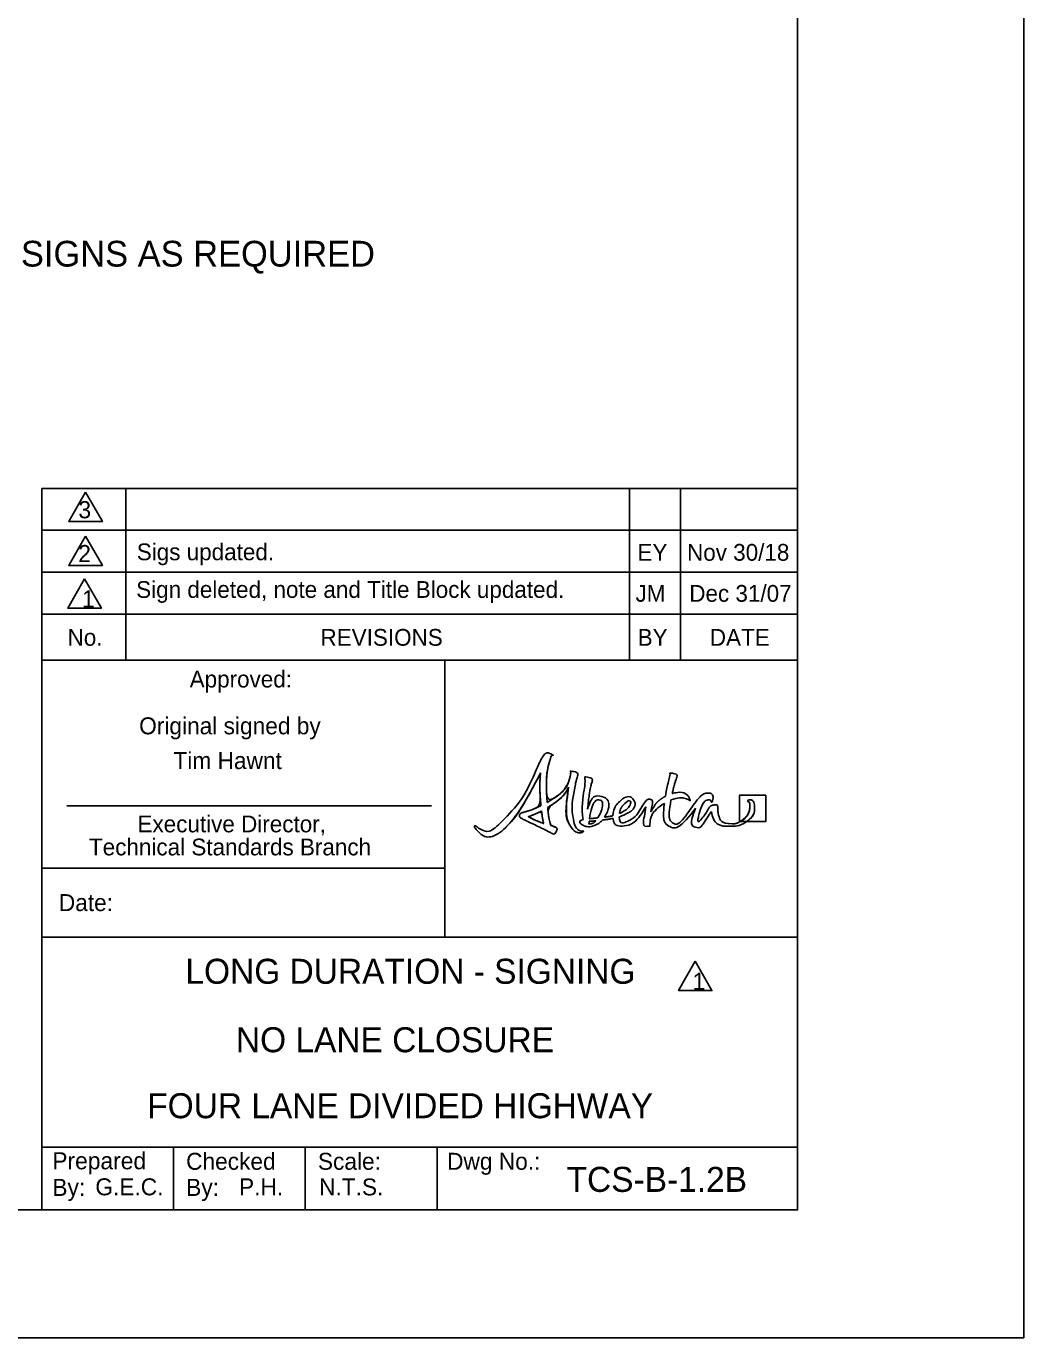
# Model space of a CAD drawing. Extents: x 1381 to 1597, y 125 to 404.
# Drawn here: x 1512.9 to 1597.2, y 124.9 to 235.9 of the extents above; entities that cross this region are included whole.
import ezdxf

# ---------------------------------------------------------------- set-up
doc = ezdxf.new("R2010")
doc.units = 0
for name, color, linetype in [('Level 10', 7, 'Continuous'), ('Level 22', 7, 'Continuous'), ('Level 44', 7, 'Continuous'), ('Level 53', 7, 'Continuous'), ('Level 60', 7, 'Continuous'), ('Level 7', 7, 'Continuous')]:
    doc.layers.add(name, color=color, linetype=linetype)

# ---------------------------------------------------------------- blocks, each defined once
blk = doc.blocks.new('Alberta Signature')
at = {"layer": 'Level 53'}
blk.add_line((-5.9, -14.5), (-13.3, -14.5), dxfattribs=at)
blk.add_lwpolyline([(-5.9, -14.5), (15.6, -14.5), (15.6, 15.2), (-14.1, 15.2), (-14.1, -14.5), (-13.3, -14.5)], dxfattribs=at)
for points, degree in [([(-192.4, -25.3), (-195.6, -24.8), (-199.8, -20.5), (-201, -13.3), (-203.3, -0.4), (-202, 12.3), (-198.2, 31.2), (-197.5, 34.8), (-195, 41), (-202.8, 42.2), (-205.3, 42.6), (-204, 41.4), (-204.7, 38.1), (-207.7, 24), (-219.2, 13.8), (-230.8, 7), (-232, 23.2), (-231.5, 41.1), (-228.5, 52.1), (-225.9, 61.4), (-222.9, 59.7), (-226.7, 61.7), (-230.6, 63.7), (-234.9, 61), (-238.4, 54.1), (-241.8, 47.2), (-257.8, 9.6), (-283.3, -15.7), (-296.3, -28.7), (-308.1, -22), (-310.5, -20), (-312.4, -18.4), (-313.1, -20.9), (-310.7, -23.5), (-300.2, -34.8), (-284.8, -28.3), (-279.2, -22.7), (-263.7, -7.2), (-245.6, 26.2), (-238.3, 40.3), (-239, 32.3), (-239.2, 19), (-237.8, 3.3), (-245.7, -0.5), (-252.7, -2.8), (-256.1, -3.7), (-259.7, -4.6), (-261.9, -6.1), (-262, -7.8), (-262.1, -9.6), (-259.6, -11.2), (-256.1, -12.8), (-249.9, -15.8), (-231.6, -24.4), (-227.1, -27), (-223.2, -29.3), (-221.3, -27.5), (-220.2, -25.1), (-218.7, -22), (-222.8, -20.2), (-226.8, -19), (-228.3, -13.7), (-229.5, -6.5), (-230.3, 1.3), (-221, 7.1), (-211.9, 14.7), (-206.6, 24.2), (-207.9, 16.3), (-211.3, -10.8), (-202.8, -22.3), (-200.9, -24.8), (-196.7, -27.5), (-192.7, -27.1), (-190.8, -26.9), (-189.8, -25.7), (-190, -25.3), (-190.2, -24.9), (-191.3, -25.5), (-192.4, -25.3)], 3), ([(-230.8, 7), (-232, 23.2), (-231.5, 41.1), (-228.5, 52.1), (-225.9, 61.4), (-222.9, 59.7), (-226.7, 61.7), (-230.6, 63.7), (-234.9, 61), (-238.4, 54.1), (-241.8, 47.2), (-257.8, 9.6), (-283.3, -15.7), (-296.3, -28.7), (-308.1, -22), (-310.5, -20), (-312.4, -18.4), (-313.1, -20.9), (-310.7, -23.5), (-300.2, -34.8), (-284.8, -28.3), (-279.2, -22.7), (-263.7, -7.2), (-245.6, 26.2), (-238.3, 40.3)], 3), ([(-238.3, 40.3), (-239, 32.3), (-239.2, 19), (-237.8, 3.3)], 2), ([(-192.4, -25.3), (-195.6, -24.8), (-199.8, -20.5), (-201, -13.3), (-203.3, -0.4), (-202, 12.3), (-198.2, 31.2), (-197.5, 34.8), (-195, 41), (-202.8, 42.2), (-205.3, 42.6), (-204, 41.4), (-204.7, 38.1), (-207.7, 24), (-219.2, 13.8), (-230.8, 7)], 3), ([(-185.2, -0.7), (-184.6, 6.9), (-183.4, 16.1), (-181.7, 24.7), (-181, 28.2), (-178.5, 34.4), (-186.3, 35.6), (-188.8, 36), (-188.4, 34.9), (-188.2, 31.5), (-187.9, 27), (-192.9, -0.2), (-190.3, -12.1)], 3), ([(-89.8, 17.1), (-89, 21.1), (-88, 25.1), (-86.9, 29.1), (-85.9, 32.6), (-82.9, 38.9), (-90.6, 40), (-93.1, 40.4), (-92, 39.2), (-92.8, 35.9), (-94.3, 29.8), (-96.2, 21.9), (-97.5, 14)], 3), ([(-230.3, 1.3), (-221, 7.1), (-211.9, 14.7), (-206.6, 24.2)], 2), ([(-206.6, 24.2), (-207.9, 16.3), (-211.3, -10.8), (-202.8, -22.3), (-200.9, -24.8), (-196.7, -27.5), (-192.7, -27.1), (-190.8, -26.9), (-189.8, -25.7), (-190, -25.3), (-190.2, -24.9), (-191.3, -25.5), (-192.4, -25.3)], 3), ([(-166.1, -9.6), (-160.5, -0.6), (-161, 11.5), (-169.1, 13.6), (-178.5, 16), (-183.2, 6.8), (-185.2, -0.7)], 3), ([(-22.5, -17.1), (-34.7, -17.1), (-37.8, -7.7), (-38.4, -3), (-38.8, 0.2), (-38.1, 4.7), (-43.5, 4.1), (-47.3, 3.7), (-50.7, -3.7), (-55.5, -9.9), (-59.6, -15.2), (-61.4, -14.7), (-60.5, -10.1), (-59.3, -4.4), (-54.5, 9), (-49.1, 10), (-46.5, 10.4), (-45.6, 6), (-44.5, 8.8), (-43.3, 11.5), (-44.4, 17.5), (-50, 17.5), (-54, 17.5), (-58.7, 13.3), (-62.6, 8.6), (-66, 4.4), (-83.1, -20.8), (-90.3, -15.4), (-93.7, -12.8), (-93.4, -2.5), (-91.3, 9.8)], 3), ([(-91.3, 9.8), (-82.8, 13), (-75.7, 12), (-71.7, 10), (-69.7, 9.1), (-69.4, 9.2), (-70.3, 11.4), (-71.5, 14.6), (-78.4, 19.6), (-89.1, 17.3), (-89.3, 17.3), (-89.6, 17.2), (-89.8, 17.1)], 3), ([(-14.1, 15.2), (-14.1, 15.2), (-14.1, -14.5), (-14.1, -14.5), (-14.1, -14.5), (-13.3, -14.5), (-13.3, -14.5), (-6.8, -10.6), (-2.5, -3.2), (-2.5, 2.8), (-2.5, 8.1), (-5.3, 7.8), (-4.9, 8.6), (-4, 10.7), (2.5, 9.5), (2.9, 2), (3.2, -4.2), (-0.1, -10.3), (-5.9, -14.5), (-5.9, -14.5), (15.6, -14.5), (15.6, -14.5), (15.6, -14.5), (15.6, 15.2), (15.6, 15.2), (15.6, 15.2), (-14.1, 15.2), (-14.1, 15.2)], 3), ([(-237.8, 3.3), (-245.7, -0.5), (-252.7, -2.8), (-256.1, -3.7), (-259.7, -4.6), (-261.9, -6.1), (-262, -7.8), (-262.1, -9.6), (-259.6, -11.2), (-256.1, -12.8), (-249.9, -15.8), (-231.6, -24.4), (-227.1, -27), (-223.2, -29.3), (-221.3, -27.5), (-220.2, -25.1), (-218.7, -22), (-222.8, -20.2), (-226.8, -19)], 3), ([(-226.8, -19), (-228.3, -13.7), (-229.5, -6.5), (-230.3, 1.3)], 2), ([(-183.2, -11.3), (-182, -1.7), (-177, 11.5), (-170.8, 9.4), (-167.3, 8.2), (-169.1, -3), (-173.7, -10.4)], 3), ([(-149.7, -9.2), (-148.4, -8.9), (-147.3, -8.5), (-146.3, -8), (-134.5, -2.8), (-130.5, 5.1), (-133.5, 9.9), (-136.3, 14.4), (-144.5, 13), (-150.9, 6.3), (-154, 2.9), (-156.5, -2.8), (-156.7, -8)], 3), ([(-156.6, -10.9), (-156, -16.2), (-152.6, -20.2), (-144.6, -19.4), (-133.4, -18.4), (-123.3, -4.5), (-119.6, 2.2)], 3), ([(-114.1, -3.7), (-113.3, 0), (-112.2, 4), (-112.1, 6.8), (-112, 9.7), (-114, 10.3), (-114.8, 10.6), (-116.4, 11), (-118.5, 10.2), (-120.5, 7.4), (-125.2, 0.7), (-131.2, -9.8), (-140.2, -14.2), (-146.7, -17.3), (-149.6, -14.1), (-149.7, -9.2)], 3), ([(-143.4, 5.7), (-139.5, 9.3), (-137.5, 9.1), (-137, 8.1), (-135.9, 6), (-140.5, -1.5), (-149.4, -5.6)], 3), ([(-149.4, -5.6), (-148.7, -1.6), (-146.5, 2.8), (-143.4, 5.7)], 2), ([(-119.6, 2.2), (-120.2, -5), (-124.9, -20.6), (-117, -19.8), (-113.8, -19.5), (-115.2, -19), (-115, -16.3), (-114.3, -6.9), (-106.5, 1.1), (-98.7, 6)], 3), ([(-97.5, 14), (-103.9, 10.4), (-109.7, 4.3), (-114.1, -3.7)], 2), ([(-98.7, 6), (-100.1, -5.6), (-99.6, -15.9), (-94.4, -19.1), (-84.7, -25.2), (-71.1, -9.3), (-63.6, 0.4)], 3), ([(-63.6, 0.4), (-67.4, -8.2), (-69.6, -19.3), (-63.8, -20.9), (-57.1, -22.9), (-51.8, -11.7), (-45.6, -3.2)], 3), ([(-13.3, -14.5), (-6.8, -10.6), (-2.5, -3.2), (-2.5, 2.8), (-2.5, 8.1), (-5.3, 7.8), (-4.9, 8.6), (-4, 10.7), (2.5, 9.5), (2.9, 2), (3.2, -4.2), (-0.1, -10.3), (-5.9, -14.5)], 3), ([(-252, -9.1), (-247.9, -7.6), (-242.7, -5.4), (-237.1, -2.5)], 2), ([(-252, -9.1), (-247.9, -7.6), (-242.7, -5.4), (-237.1, -2.5), (-236.4, -8.8), (-235.6, -13.4), (-234.7, -16.8), (-238.7, -15.3), (-244.5, -13), (-252, -9.1)], 3), ([(-234.7, -16.8), (-238.7, -15.3), (-244.5, -13), (-252, -9.1)], 2), ([(-237.1, -2.5), (-236.4, -8.8), (-235.6, -13.4), (-234.7, -16.8)], 2), ([(-190.3, -12.1), (-193.6, -13.2), (-195, -15.7), (-190.7, -18.4), (-187.7, -20.2), (-181.2, -20.8), (-174.6, -17.5), (-172.2, -16.4), (-170.2, -14.7), (-168.5, -12.8)], 3), ([(-184.2, -17), (-183.8, -16.7), (-183.5, -16.1), (-183.5, -15.5), (-183.5, -15.1), (-183.5, -14.7), (-183.5, -14.2)], 3), ([(-183.5, -14.2), (-181.8, -14.2), (-179.2, -14), (-176.1, -13.7)], 2), ([(-173.7, -10.4), (-176.7, -10.7), (-179.9, -11), (-183.2, -11.3)], 2), ([(-176.1, -13.7), (-177.7, -15.5), (-179.6, -16.7), (-181.5, -17)], 2), ([(-168.5, -12.8), (-164.5, -12.3), (-160.4, -11.7), (-156.6, -10.9)], 2), ([(-156.7, -8), (-159.5, -8.6), (-162.6, -9.1), (-166.1, -9.6)], 2), ([(-45.6, -3.2), (-44.9, -9.3), (-40.8, -19.9), (-24.3, -19.9), (-16.9, -19.9), (-10.6, -17.8), (-5.9, -14.5)], 3), ([(-13.3, -14.5), (-16, -16.1), (-19.1, -17.1), (-22.5, -17.1)], 2), ([(-181.5, -17), (-182.6, -17.2), (-183.5, -17.2), (-184.2, -17)], 2)]:
    blk.add_open_spline(points, degree=degree, dxfattribs=at)

msp = doc.modelspace()

# ---------------------------------------------------------------- linework, layer by layer
at = {"layer": 'Level 22'}
msp.add_line((1578.06, 393.17), (1578.06, 135.75), dxfattribs=at)
at = {"layer": 'Level 60'}
for p, q in [((1514.18, 190.31), (1514.18, 196.78)), ((1578.06, 196.78), (1514.18, 196.78)), ((1514.18, 190.31), (1514.18, 196.78)), ((1578.06, 196.78), (1514.18, 196.78)), ((1521.27, 190.31), (1521.27, 196.78)), ((1521.27, 190.31), (1521.27, 196.78)), ((1563.86, 196.78), (1563.86, 182.24)), ((1563.86, 196.78), (1563.86, 182.24)), ((1568.17, 196.78), (1568.17, 182.24)), ((1568.17, 196.78), (1568.17, 182.24)), ((1578.06, 193.24), (1514.18, 193.24)), ((1578.06, 193.24), (1514.18, 193.24)), ((1514.18, 182.24), (1514.18, 190.31)), ((1514.18, 182.24), (1514.18, 190.31)), ((1578.06, 189.69), (1514.18, 189.69)), ((1578.06, 189.69), (1514.18, 189.69)), ((1521.27, 182.24), (1521.27, 190.31)), ((1521.27, 182.24), (1521.27, 190.31)), ((1578.06, 186.14), (1514.18, 186.14)), ((1578.06, 186.14), (1514.18, 186.14)), ((1514.18, 135.75), (1514.18, 182.24)), ((1514.18, 182.24), (1578.06, 182.24)), ((1514.18, 182.24), (1578.06, 182.24)), ((1548.25, 182.24), (1548.25, 158.81)), ((1548.25, 182.24), (1548.25, 182.24)), ((1548.25, 182.24), (1548.25, 182.24)), ((1548.25, 182.24), (1548.25, 182.24)), ((1578.06, 182.24), (1578.06, 135.75)), ((1516.29, 169.92), (1547.11, 169.92)), ((1514.18, 164.67), (1548.25, 164.67)), ((1514.18, 158.81), (1578.06, 158.81)), ((1514.18, 141.07), (1578.06, 141.07)), ((1525.32, 135.75), (1525.32, 141.07)), ((1536.45, 135.75), (1536.45, 141.07)), ((1547.59, 141.07), (1547.59, 135.75)), ((1529.67, 135.75), (1529.67, 135.75)), ((1578.06, 135.75), (1578.06, 135.75)), ((1578.06, 135.75), (1578.06, 135.75))]:
    msp.add_line(p, q, dxfattribs=at)
for points in [[(1597.18, 403.94), (1381.18, 403.94), (1381.18, 124.94), (1597.18, 124.94)], [(1578.06, 393.13), (1391.18, 393.13), (1391.18, 135.75), (1578.06, 135.75)], [(1517.8, 189.12), (1516.38, 186.65), (1519.22, 186.65)], [(1517.8, 189.12), (1516.38, 186.65), (1519.22, 186.65)], [(1569.41, 156.78), (1568, 154.31), (1570.83, 154.31)]]:
    msp.add_lwpolyline(points, close=True, dxfattribs=at)
for points in [[(1517.88, 196.45), (1516.49, 194.03)], [(1517.88, 196.45), (1516.49, 194.03)], [(1519.28, 194.03), (1517.88, 196.45)], [(1516.49, 194.03), (1516.46, 193.98), (1519.3, 193.98), (1519.28, 194.03)], [(1516.49, 194.03), (1516.46, 193.98), (1519.3, 193.98), (1519.28, 194.03)], [(1517.88, 192.74), (1516.49, 190.31)], [(1517.88, 192.74), (1516.49, 190.31)], [(1519.28, 190.31), (1517.88, 192.74)], [(1516.49, 190.31), (1516.46, 190.27), (1519.3, 190.27), (1519.28, 190.31)], [(1516.49, 190.31), (1516.46, 190.27), (1519.3, 190.27), (1519.28, 190.31)]]:
    msp.add_lwpolyline(points, dxfattribs=at)

# ---------------------------------------------------------------- block references
at = {"layer": 'Level 60', "xscale": 0.075, "yscale": 0.075}
msp.add_blockref('Alberta Signature', (1574.21, 169.69), dxfattribs=at)

# ---------------------------------------------------------------- texts
at = {"layer": 'Level 10'}
msp.add_text('ADDITIONAL WARNING SIGNS AS REQUIRED', height=2.177, rotation=360, dxfattribs=at).set_placement((1479.26, 215.54))
at = {"layer": 'Level 44'}
for s, p in [('EY', (1564.53, 190.66)), ('Nov 30/18', (1568.72, 190.66))]:
    msp.add_text(s, height=1.419, rotation=360, dxfattribs=at).set_placement(p)
at = {"layer": 'Level 60'}
for s, height, p in [('3', 1.45, (1517.27, 194.25)), ('3', 1.45, (1517.27, 194.25)), ('2', 1.45, (1517.26, 190.54)), ('2', 1.45, (1517.26, 190.54)), ('JM', 1.419, (1564.37, 187.19)), ('Dec 31/07', 1.419, (1568.91, 187.19)), ('1', 1.45, (1517.58, 186.71)), ('1', 1.45, (1517.58, 186.71)), ('No.', 1.419, (1516.36, 183.47)), ('No.', 1.419, (1516.36, 183.47)), ('REVISIONS', 1.419, (1537.74, 183.47)), ('REVISIONS', 1.419, (1537.74, 183.47)), ('BY', 1.419, (1564.55, 183.47)), ('BY', 1.419, (1564.55, 183.47)), ('DATE', 1.419, (1570.65, 183.47)), ('DATE', 1.419, (1570.65, 183.47)), ('Date:', 1.434, (1515.62, 161.03)), ('LONG DURATION - SIGNING', 2.116, (1526.32, 154.88)), ('1', 1.45, (1569.19, 154.36)), ('NO LANE CLOSURE', 2.116, (1530.59, 149.09)), ('FOUR LANE DIVIDED HIGHWAY', 2.116, (1523.09, 143.51)), ('Prepared', 1.441, (1515.07, 139.19)), ('Checked', 1.434, (1526.38, 139.15)), ('Scale:', 1.434, (1537.52, 139.15)), ('Dwg No.:', 1.434, (1548.44, 139.15)), ('By:', 1.441, (1515.07, 136.94)), ('G.E.C.', 1.434, (1518.71, 136.99)), ('By:', 1.441, (1526.38, 136.94)), ('P.H.', 1.434, (1530.85, 136.99)), ('    N.T.S.   ', 1.4336, (1535.49, 136.98))]:
    msp.add_text(s, height=height, rotation=360, dxfattribs=at).set_placement(p)
for s, height, p in [('Sign deleted, note and Title Block updated.', 1.419, (1522.16, 187.52)), ('Approved:', 1.419, (1526.68, 179.94)), ('Original signed by', 1.434, (1522.41, 175.98)), ('Tim Hawnt', 1.434, (1525.31, 173.04)), ('Executive Director,', 1.4194, (1522.27, 167.69)), ('Technical Standards Branch', 1.4194, (1518.17, 165.74)), ('TCS-B-1.2B', 2.116, (1558.54, 137.28))]:
    msp.add_text(s, height=height, dxfattribs=at).set_placement(p)
at = {"layer": 'Level 7'}
msp.add_text('Sigs updated.', height=1.419, dxfattribs=at).set_placement((1522.21, 190.7))

doc.saveas('drawing.dxf')
